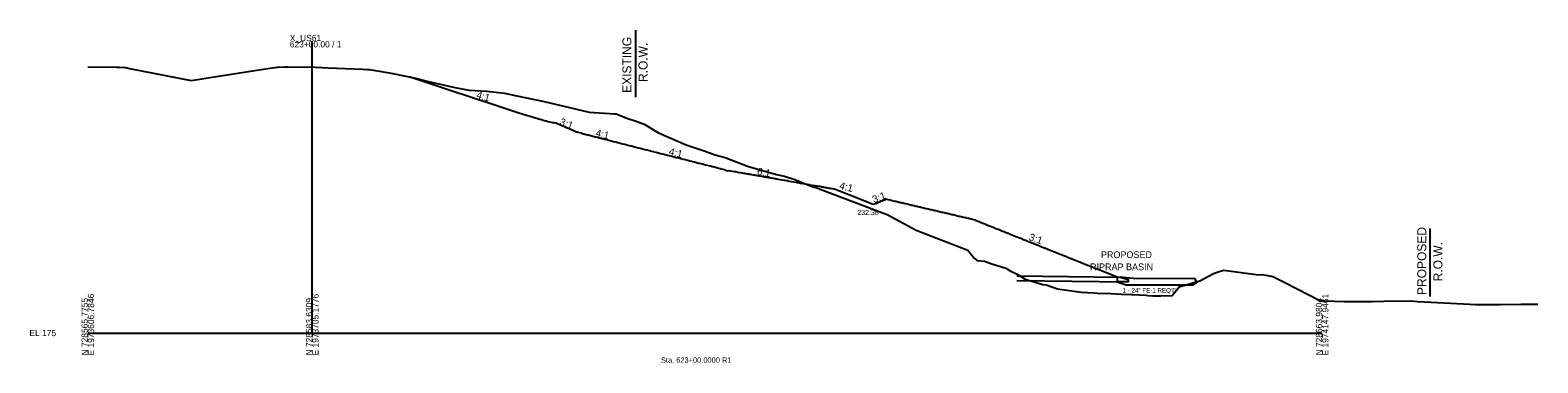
# Model space of a CAD drawing. Extents: x -26 to 1629, y -25 to 9635.
# Drawn here: x -26 to 646, y 7487 to 7635 of the extents above; entities that cross this region are included whole.
import ezdxf

# ---------------------------------------------------------------- set-up
doc = ezdxf.new("R2010")
doc.units = 0
for name, color, linetype in [('1', 7, 'Continuous'), ('Default', 7, 'Continuous'), ('Draft_XS_Grid', 7, 'Continuous'), ('Draft_XS_Text', 7, 'Continuous'), ('DTM CONTOURS_MAJOR', 7, 'Continuous'), ('DTM_X_GROUND', 7, 'Continuous'), ('XS_CELL', 7, 'Continuous'), ('XS_P_DRAINAGE', 7, 'Continuous'), ('XS_P_GROUND', 7, 'Continuous'), ('XS_P_ROW', 7, 'Continuous'), ('XS_P_TX_DCH', 7, 'Continuous'), ('XS_P_TX_FS_BS', 7, 'Continuous'), ('XS_X_ROW', 7, 'Continuous')]:
    doc.layers.add(name, color=color, linetype=linetype)

msp = doc.modelspace()

# ---------------------------------------------------------------- linework, layer by layer
at = {"layer": '1'}
msp.add_lwpolyline([(458.71, 7522.84), (462.72, 7521.39), (492.72, 7521.39), (494.17, 7522.52), (493.37, 7524.14), (465.76, 7524.29), (459.97, 7524.83), (463.61, 7523.8), (463.6, 7522.82)], close=True, dxfattribs=at)
at = {"layer": 'DTM_X_GROUND'}
msp.add_lwpolyline([(0, 7618.63), (12.87, 7618.4), (13.12, 7618.4), (14.14, 7618.35), (16.71, 7618.22), (16.89, 7618.21), (18.54, 7617.89), (46.1, 7612.5), (50.76, 7613.22), (60.21, 7614.67), (72.42, 7616.58), (81.17, 7617.92), (84.4, 7618.42), (84.69, 7618.44), (87.72, 7618.61), (89.08, 7618.59), (101.48, 7618.39), (107.05, 7618.16), (122.46, 7617.54), (124.43, 7617.4), (125.51, 7617.33), (129.91, 7616.58), (135.91, 7615.59), (146.07, 7613.51), (151.87, 7612.05), (163.59, 7609.37), (169.86, 7608.24), (177.81, 7607.74), (185.66, 7606.76), (191.19, 7605.7), (203.34, 7603.18), (223.39, 7598.39), (234.7, 7597.66), (235.46, 7597.57), (238.36, 7596.39), (240.14, 7595.66), (244.28, 7594.32), (247.95, 7592.96), (254.29, 7589.2), (266.67, 7583.88), (275.12, 7581), (279.58, 7579.33), (284.02, 7578.23), (293.96, 7574.3), (306.83, 7570.63), (310.41, 7569.85), (315.09, 7568.41), (323.31, 7564.99), (324.46, 7564.77), (325.32, 7564.46), (326.34, 7564.09), (355.68, 7552.95), (356.13, 7552.79), (369.03, 7545.78), (392.09, 7536.86), (394.87, 7533.35), (396.26, 7532.25), (399.56, 7531.93), (402.76, 7530.79), (409.08, 7528.89), (410.94, 7527.65), (414.09, 7526.21), (417.62, 7524), (425.53, 7521.62), (427.03, 7521.43), (432.04, 7519.67), (436.41, 7519.08), (441.55, 7518.4), (442.71, 7518.24), (445.43, 7518.02), (448.44, 7517.94), (449.86, 7517.82), (455.9, 7517.63), (460.59, 7517.35), (465.06, 7517.19), (465.5, 7517.16), (471.37, 7516.79), (472.25, 7516.74), (474.6, 7516.53), (475.38, 7516.6), (477.99, 7516.59), (478.09, 7516.59), (483.12, 7516.77), (486.23, 7520.63), (495.55, 7523.26), (501.64, 7526.44), (503.68, 7527.18), (505.53, 7527.86), (506.14, 7527.93), (521.57, 7525.9), (523.28, 7526.01), (527.98, 7525.14), (533.01, 7522.58), (538.79, 7519.65), (549.22, 7514.36), (551.1, 7514.31), (559.75, 7514.04), (572.26, 7514.1), (577.48, 7514.19), (589.66, 7514.31), (592.54, 7514.07), (601.44, 7513.62), (615.73, 7512.84), (618.13, 7512.66), (622.52, 7512.72), (628.85, 7512.68), (629.32, 7512.67), (638.46, 7512.84), (646.1, 7512.89)], dxfattribs=at)
at = {"layer": 'XS_CELL'}
for p, q in [((100, 7500), (100, 7630)), ((0, 7500), (100, 7500)), ((100, 7500), (550, 7500))]:
    msp.add_line(p, q, dxfattribs=at)
at = {"layer": 'XS_P_DRAINAGE'}
for p, q in [((413.91, 7525.41), (459.97, 7524.83)), ((458.65, 7524.86), (458.63, 7522.86)), ((459.97, 7524.83), (463.61, 7523.8)), ((413.88, 7523.41), (462.91, 7522.8)), ((463.61, 7523.8), (463.6, 7522.82))]:
    msp.add_line(p, q, dxfattribs=at)
at = {"layer": 'XS_P_GROUND'}
for points in [[(219.88, 7588.99), (218.91, 7589.23), (218.85, 7589.24), (218.79, 7589.26), (218.13, 7589.43), (217.84, 7589.53), (217.82, 7589.53), (217.24, 7589.73), (217.22, 7589.74), (217.2, 7589.75), (216.79, 7589.93), (216.69, 7589.97), (215.76, 7590.38), (215.03, 7590.7), (214.93, 7590.74), (214.73, 7590.83), (214.55, 7590.9), (213.7, 7591.28), (213.7, 7591.28), (213.7, 7591.28), (213.7, 7591.28), (213.7, 7591.28), (213.7, 7591.28), (213.7, 7591.28), (213.69, 7591.28), (213.69, 7591.28), (213.69, 7591.28), (213.69, 7591.28), (213.69, 7591.28), (213.69, 7591.28), (213.69, 7591.28), (213.69, 7591.28), (213.68, 7591.28), (213.68, 7591.28), (213.67, 7591.29), (213.67, 7591.29), (213.67, 7591.29), (213.67, 7591.29), (213.65, 7591.3), (213.63, 7591.3), (213.62, 7591.31), (213.61, 7591.31), (213.61, 7591.31), (213.61, 7591.31), (213.13, 7591.52), (212.66, 7591.73), (212.13, 7591.96), (211.63, 7592.18), (211, 7592.45), (210.6, 7592.63), (210.14, 7592.83), (209.57, 7593.07), (209, 7593.32), (208.72, 7593.45), (208.38, 7593.48), (208.23, 7593.5), (208.22, 7593.5), (207.71, 7593.58), (207.7, 7593.58), (207.16, 7593.68), (207.15, 7593.68), (206.64, 7593.79), (206.55, 7593.8), (206.54, 7593.8), (205.91, 7593.93), (205.84, 7593.94), (205.17, 7594.09), (205.04, 7594.12), (204.33, 7594.29), (204.1, 7594.35), (203.32, 7594.55), (202.94, 7594.65), (202.09, 7594.89), (201.46, 7595.06), (200.52, 7595.34), (199.48, 7595.64), (198.42, 7595.97), (196.62, 7596.52), (195.41, 7596.9), (192.09, 7597.95), (190.65, 7598.42), (183.55, 7600.72), (181.86, 7601.28), (160.94, 7608.18), (159.63, 7608.62), (143.17, 7614.1)], [(219.88, 7588.99), (219.88, 7588.99), (219.88, 7588.99), (220.04, 7588.95), (220.91, 7588.73), (221.16, 7588.66), (221.94, 7588.47), (222.6, 7588.3), (222.97, 7588.21), (223.41, 7588.1), (224, 7587.95), (224.54, 7587.82), (225.03, 7587.69), (225.66, 7587.54), (226.06, 7587.43), (226.41, 7587.35), (227.1, 7587.18), (227.91, 7586.97), (228.13, 7586.92), (229.03, 7586.69), (229.16, 7586.66), (229.93, 7586.46), (229.98, 7586.45), (229.99, 7586.45), (230, 7586.45), (230.2, 7586.4), (230.21, 7586.4), (231.17, 7586.15), (231.21, 7586.14), (231.25, 7586.13), (232.21, 7585.88), (233.18, 7585.63), (233.21, 7585.62), (233.24, 7585.62), (234.21, 7585.36), (234.23, 7585.36), (235.21, 7585.11), (236.2, 7584.85), (236.21, 7584.85), (236.22, 7584.84), (237.21, 7584.59), (238.21, 7584.33), (238.21, 7584.33), (238.22, 7584.33), (239.1, 7584.1)], [(239.1, 7584.1), (239.21, 7584.07), (239.21, 7584.07), (240.21, 7583.82), (240.21, 7583.82), (241.21, 7583.57), (241.22, 7583.56), (242.21, 7583.31), (242.22, 7583.31), (243.21, 7583.06), (243.22, 7583.06), (244.21, 7582.81), (244.23, 7582.8), (245.21, 7582.55), (245.23, 7582.55), (246.21, 7582.3), (246.23, 7582.29), (247.21, 7582.05), (247.23, 7582.04), (248.21, 7581.79), (248.24, 7581.79), (249.21, 7581.54), (249.24, 7581.53), (250.21, 7581.29), (250.24, 7581.28), (251.21, 7581.03), (251.25, 7581.03), (252.21, 7580.78), (252.25, 7580.77), (253.21, 7580.53), (253.25, 7580.52), (254.21, 7580.27), (254.25, 7580.26), (255.21, 7580.02), (255.26, 7580.01), (256.21, 7579.77), (256.26, 7579.76), (257.21, 7579.52), (257.26, 7579.5), (258.21, 7579.26), (258.27, 7579.25), (259.21, 7579.01), (259.27, 7578.99), (260.21, 7578.76), (260.27, 7578.74), (261.21, 7578.5), (261.27, 7578.49), (262.21, 7578.25), (262.28, 7578.23), (263.21, 7578), (263.28, 7577.98), (264.21, 7577.74), (264.28, 7577.73), (265.21, 7577.49), (265.29, 7577.47), (266.21, 7577.24), (266.29, 7577.22), (267.21, 7576.98), (267.29, 7576.96), (268.21, 7576.73), (268.29, 7576.71), (269.21, 7576.48), (269.3, 7576.46), (270.21, 7576.22), (270.3, 7576.2), (271.21, 7575.97), (271.3, 7575.95), (272.21, 7575.72), (272.31, 7575.69), (273.21, 7575.46), (273.32, 7575.44), (274.21, 7575.21), (274.34, 7575.18), (275.21, 7574.96), (275.36, 7574.92), (276.21, 7574.7), (276.38, 7574.66), (277.21, 7574.45), (277.41, 7574.4), (278.21, 7574.2), (278.45, 7574.14), (279.22, 7573.95), (279.51, 7573.87), (280.22, 7573.69), (280.6, 7573.6), (281.22, 7573.44), (281.75, 7573.3), (282.22, 7573.19), (283.07, 7572.97), (283.22, 7572.93), (283.47, 7572.87)], [(283.47, 7572.87), (283.57, 7572.83), (284.36, 7572.51), (285, 7572.26), (285.37, 7572.41), (285.42, 7572.42)], [(285.42, 7572.42), (286.31, 7572.27), (286.96, 7572.15), (287.32, 7572.09), (288.1, 7571.96), (288.33, 7571.92), (288.56, 7571.88), (289.34, 7571.74), (289.6, 7571.69), (290.35, 7571.56), (290.63, 7571.51), (291.36, 7571.39), (291.67, 7571.33), (292.37, 7571.21), (292.71, 7571.15), (293.38, 7571.03), (293.75, 7570.97), (294.39, 7570.86), (294.79, 7570.79), (295.4, 7570.68), (295.83, 7570.61), (296.41, 7570.5), (296.87, 7570.42), (297.42, 7570.33), (297.91, 7570.24), (298.43, 7570.15), (298.95, 7570.06), (299.44, 7569.98), (299.99, 7569.88), (300.45, 7569.8), (301.03, 7569.7), (301.46, 7569.62), (302.07, 7569.52), (302.47, 7569.45), (303.11, 7569.33), (303.48, 7569.27), (304.15, 7569.15), (304.49, 7569.09), (305.19, 7568.97), (305.5, 7568.92), (306.23, 7568.79), (306.51, 7568.74), (307.27, 7568.61), (307.52, 7568.56), (308.31, 7568.43), (308.53, 7568.39), (309.35, 7568.25), (309.54, 7568.21), (310.39, 7568.06), (310.55, 7568.04), (311.43, 7567.88), (311.56, 7567.86), (312.47, 7567.7), (312.57, 7567.68), (313.51, 7567.52), (313.58, 7567.51), (314.55, 7567.34), (314.59, 7567.33), (315.59, 7567.16), (315.6, 7567.15), (316.08, 7567.07), (316.61, 7566.98), (316.62, 7566.98), (317.62, 7566.8), (317.65, 7566.8), (318.63, 7566.62), (318.68, 7566.62), (319.64, 7566.45), (319.71, 7566.44), (320.65, 7566.27), (320.74, 7566.26), (321.66, 7566.1), (321.78, 7566.07), (322.67, 7565.92), (322.82, 7565.89), (323.68, 7565.74), (323.87, 7565.71), (324.69, 7565.57), (324.92, 7565.53), (325.7, 7565.39), (325.98, 7565.34), (326.71, 7565.21), (327.05, 7565.15), (327.72, 7565.04), (328.13, 7564.97), (328.73, 7564.86), (329.22, 7564.78), (329.74, 7564.68), (330.34, 7564.58), (330.75, 7564.51), (331.49, 7564.38), (331.76, 7564.33), (332.68, 7564.17), (332.77, 7564.16), (333.18, 7564.08)], [(333.18, 7564.08), (334.53, 7563.54), (335.45, 7563.18), (336.37, 7562.81), (339.16, 7561.69), (341.02, 7560.95), (342.89, 7560.2), (344, 7559.76), (345.71, 7559.07), (346.65, 7558.7), (346.68, 7558.68), (348.71, 7557.87), (349.49, 7557.56), (350, 7557.36), (351.39, 7557.91), (353.3, 7558.67), (355.43, 7559.53), (355.47, 7559.54), (355.54, 7559.57)], [(395.54, 7550.24), (394.55, 7550.47), (394.47, 7550.49), (393.55, 7550.7), (393.39, 7550.74), (392.55, 7550.94), (392.33, 7550.99), (391.55, 7551.17), (391.27, 7551.23), (390.55, 7551.4), (390.23, 7551.48), (389.55, 7551.64), (389.19, 7551.72), (388.55, 7551.87), (388.15, 7551.96), (387.55, 7552.1), (387.12, 7552.2), (386.55, 7552.34), (386.09, 7552.44), (385.55, 7552.57), (385.06, 7552.68), (384.55, 7552.8), (384.04, 7552.92), (383.55, 7553.04), (383.02, 7553.16), (382.55, 7553.27), (382, 7553.4), (381.55, 7553.5), (380.98, 7553.64), (380.55, 7553.74), (379.96, 7553.87), (379.55, 7553.97), (378.95, 7554.11), (378.55, 7554.2), (377.93, 7554.35), (377.55, 7554.43), (376.92, 7554.58), (376.55, 7554.67), (375.91, 7554.82), (375.55, 7554.9), (374.89, 7555.05), (374.55, 7555.13), (373.88, 7555.29), (373.55, 7555.37), (372.87, 7555.53), (372.55, 7555.6), (371.86, 7555.76), (371.55, 7555.83), (370.85, 7556), (370.55, 7556.07), (369.85, 7556.23), (369.55, 7556.3), (369.24, 7556.37), (368.55, 7556.53), (368.23, 7556.61), (367.55, 7556.77), (367.21, 7556.85), (366.55, 7557), (366.19, 7557.09), (365.55, 7557.23), (365.16, 7557.32), (364.55, 7557.47), (364.14, 7557.56), (363.55, 7557.7), (363.11, 7557.8), (362.55, 7557.93), (362.07, 7558.05), (361.55, 7558.17), (361.03, 7558.29), (360.55, 7558.4), (359.98, 7558.53), (359.55, 7558.63), (358.92, 7558.78), (358.55, 7558.87), (357.85, 7559.03), (357.55, 7559.1), (356.76, 7559.29), (356.55, 7559.33), (355.56, 7559.57), (355.55, 7559.57), (355.54, 7559.57)], [(395.54, 7550.24), (396.32, 7549.93), (396.53, 7549.84), (396.63, 7549.8), (397.13, 7549.6), (397.25, 7549.56), (397.73, 7549.36), (398.13, 7549.21), (398.78, 7548.95), (399.21, 7548.77), (399.33, 7548.72), (399.7, 7548.58), (400.14, 7548.4), (401.3, 7547.93), (401.67, 7547.79), (402.32, 7547.53), (402.48, 7547.46), (403.39, 7547.1), (403.52, 7547.05), (403.64, 7547), (404.45, 7546.68), (404.46, 7546.67), (404.62, 7546.61), (405.5, 7546.25), (405.63, 7546.2), (406.04, 7546.04), (406.38, 7545.9), (406.59, 7545.82), (406.68, 7545.78), (407.61, 7545.41), (408.24, 7545.16), (408.56, 7545.03), (408.68, 7544.98), (409.22, 7544.77), (410.12, 7544.41), (410.52, 7544.25), (410.72, 7544.17), (410.8, 7544.13), (411.33, 7543.92), (412.49, 7543.46), (412.94, 7543.28), (412.95, 7543.27), (413.48, 7543.06), (414.15, 7542.8), (414.46, 7542.67), (415.08, 7542.42), (415.22, 7542.37), (416.43, 7541.88), (416.53, 7541.84), (417.23, 7541.56), (417.38, 7541.5), (417.41, 7541.49), (418.25, 7541.15), (418.4, 7541.1), (419.09, 7540.82), (419.54, 7540.64), (420.33, 7540.32), (420.47, 7540.27), (421.56, 7539.83), (421.72, 7539.77), (422.33, 7539.52), (423.44, 7539.08), (423.73, 7538.96), (424.3, 7538.74), (424.82, 7538.53), (425, 7538.46), (426.27, 7537.95), (426.38, 7537.91), (427.01, 7537.65), (427.11, 7537.61), (427.6, 7537.42), (428.58, 7537.02), (429.21, 7536.77), (429.41, 7536.69), (430.05, 7536.44), (430.21, 7536.37), (430.78, 7536.14), (431.19, 7535.98), (431.52, 7535.85), (431.63, 7535.81), (432.52, 7535.45), (432.99, 7535.26), (433.16, 7535.19), (433.63, 7535), (433.85, 7534.91), (434.46, 7534.67), (435.19, 7534.38), (436.09, 7534.02), (436.66, 7533.79), (436.97, 7533.67), (438.08, 7533.22), (438.13, 7533.2), (438.34, 7533.12), (439.21, 7532.77), (439.46, 7532.67), (439.6, 7532.62), (440.05, 7532.44), (441.46, 7531.87), (441.73, 7531.77), (441.8, 7531.74), (442.01, 7531.65), (443.98, 7530.86), (444, 7530.86), (444.74, 7530.56), (444.84, 7530.52), (445.14, 7530.4), (445.95, 7530.08), (445.98, 7530.07), (447.42, 7529.49), (448.9, 7528.89), (449.39, 7528.7), (449.72, 7528.57), (450.87, 7528.11), (451.68, 7527.79), (452.03, 7527.64), (459.03, 7524.84)]]:
    msp.add_lwpolyline(points, dxfattribs=at)
at = {"layer": 'XS_P_ROW'}
msp.add_line((598, 7546.54), (598, 7516.22), dxfattribs=at)
at = {"layer": 'XS_X_ROW'}
msp.add_line((244, 7634.9), (244, 7605), dxfattribs=at)

# ---------------------------------------------------------------- texts
at = {"layer": '1'}
for s, p in [('RIPRAP BASIN', (446.58, 7527.97)), ('PROPOSED', (451.43, 7533.37))]:
    msp.add_text(s, height=3, dxfattribs=at).set_placement(p)
at = {"layer": 'Default'}
for p in [(218.09, 7589.37), (494.46, 7517)]:
    msp.add_text('X', height=0.12, dxfattribs=at).set_placement(p)
at = {"layer": 'Draft_XS_Grid'}
msp.add_text('-', height=0.0001, dxfattribs=at).set_placement((0, 7500))
at = {"layer": 'Draft_XS_Text'}
msp.add_text('Sta. 623+00.0000 R1', height=2.4, dxfattribs=at).set_placement((255.38, 7486.75))
at = {"layer": 'DTM CONTOURS_MAJOR'}
for p in [(121.96, 7617.5), (205.63, 7593.73), (239.06, 7584.04), (239.06, 7584.04), (283.43, 7572.81), (284.96, 7572.2), (285.38, 7572.36), (316.04, 7567.01), (343.96, 7559.7), (349.96, 7557.3)]:
    msp.add_text('X', height=0.12, dxfattribs=at).set_placement(p)
at = {"layer": 'XS_CELL'}
for s, p in [('X_US61', (90, 7630)), ('623+00.00 / 1', (90, 7627.2)), ('EL 175', (-26, 7498.6))]:
    msp.add_text(s, height=2.8, dxfattribs=at).set_placement(p)
for s, p in [('N 728565.7755', (0, 7490)), ('E 1973606.7846', (2.8, 7490)), ('N 728583.6309', (100, 7490)), ('E 1973705.1776', (102.8, 7490)), ('N 728663.9804', (550, 7490)), ('E 1974147.9461', (552.8, 7490))]:
    msp.add_text(s, height=2.8, rotation=90, dxfattribs=at).set_placement(p)
at = {"layer": 'XS_P_DRAINAGE'}
msp.add_text('1 - 24" FE-1 REQ\'D', height=2, dxfattribs=at).set_placement((461.07, 7518))
at = {"layer": 'XS_P_ROW'}
for s, p in [('PROPOSED', (596.37, 7516.93)), ('R.O.W.', (603.57, 7523))]:
    msp.add_text(s, height=4, rotation=90, dxfattribs=at).set_placement(p)
at = {"layer": 'XS_P_TX_DCH'}
msp.add_text('232.36', height=2.25, dxfattribs=at).set_placement((342.88, 7552.55))
at = {"layer": 'XS_P_TX_FS_BS'}
for s, rotation, p in [('4:1', 344.31311, (172.88, 7604.69)), ('3:1', 339.21855, (209.91, 7592.86)), ('4:1', 345.75301, (226.02, 7587.73)), ('4:1', 345.79426, (258.69, 7579.45)), ('6:1', 350.09577, (298.01, 7570.53)), ('4:1', 345.31911, (334.64, 7564.28)), ('3:1', 21.80141, (350.33, 7557.81)), ('3:1', 340.76082, (419.06, 7541.46))]:
    msp.add_text(s, height=3.24, rotation=rotation, dxfattribs=at).set_placement(p)
at = {"layer": 'XS_X_ROW'}
for s, p in [('EXISTING', (242.19, 7606.94)), ('R.O.W.', (249.39, 7611.78))]:
    msp.add_text(s, height=4, rotation=90, dxfattribs=at).set_placement(p)

doc.saveas('drawing.dxf')
